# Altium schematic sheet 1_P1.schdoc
size 307 x 218 mm; Symbol: Sheet-Symbol_A4; Device: Sheet-Symbol_A4; @Project Name: Project Name; @Page Count: 3; @Update Date: 2021.11.05; @Create Date: 2024-11-23; @Schematic Name: Schematic Name; @Page No: 1; @Page Name: P1; Company: EasyEDA.com; Version: V1.0; Page Size: A4; @Create Time: 2:30:59 PM; @Update Time: 1:48:49 AM; Title Block Position: 3; Width: 1170; Height: 825; Region Start: 1; X Region Count: 6; Y Region Count: 4; Blade Width: 10; @Board Name: PENTASLAM
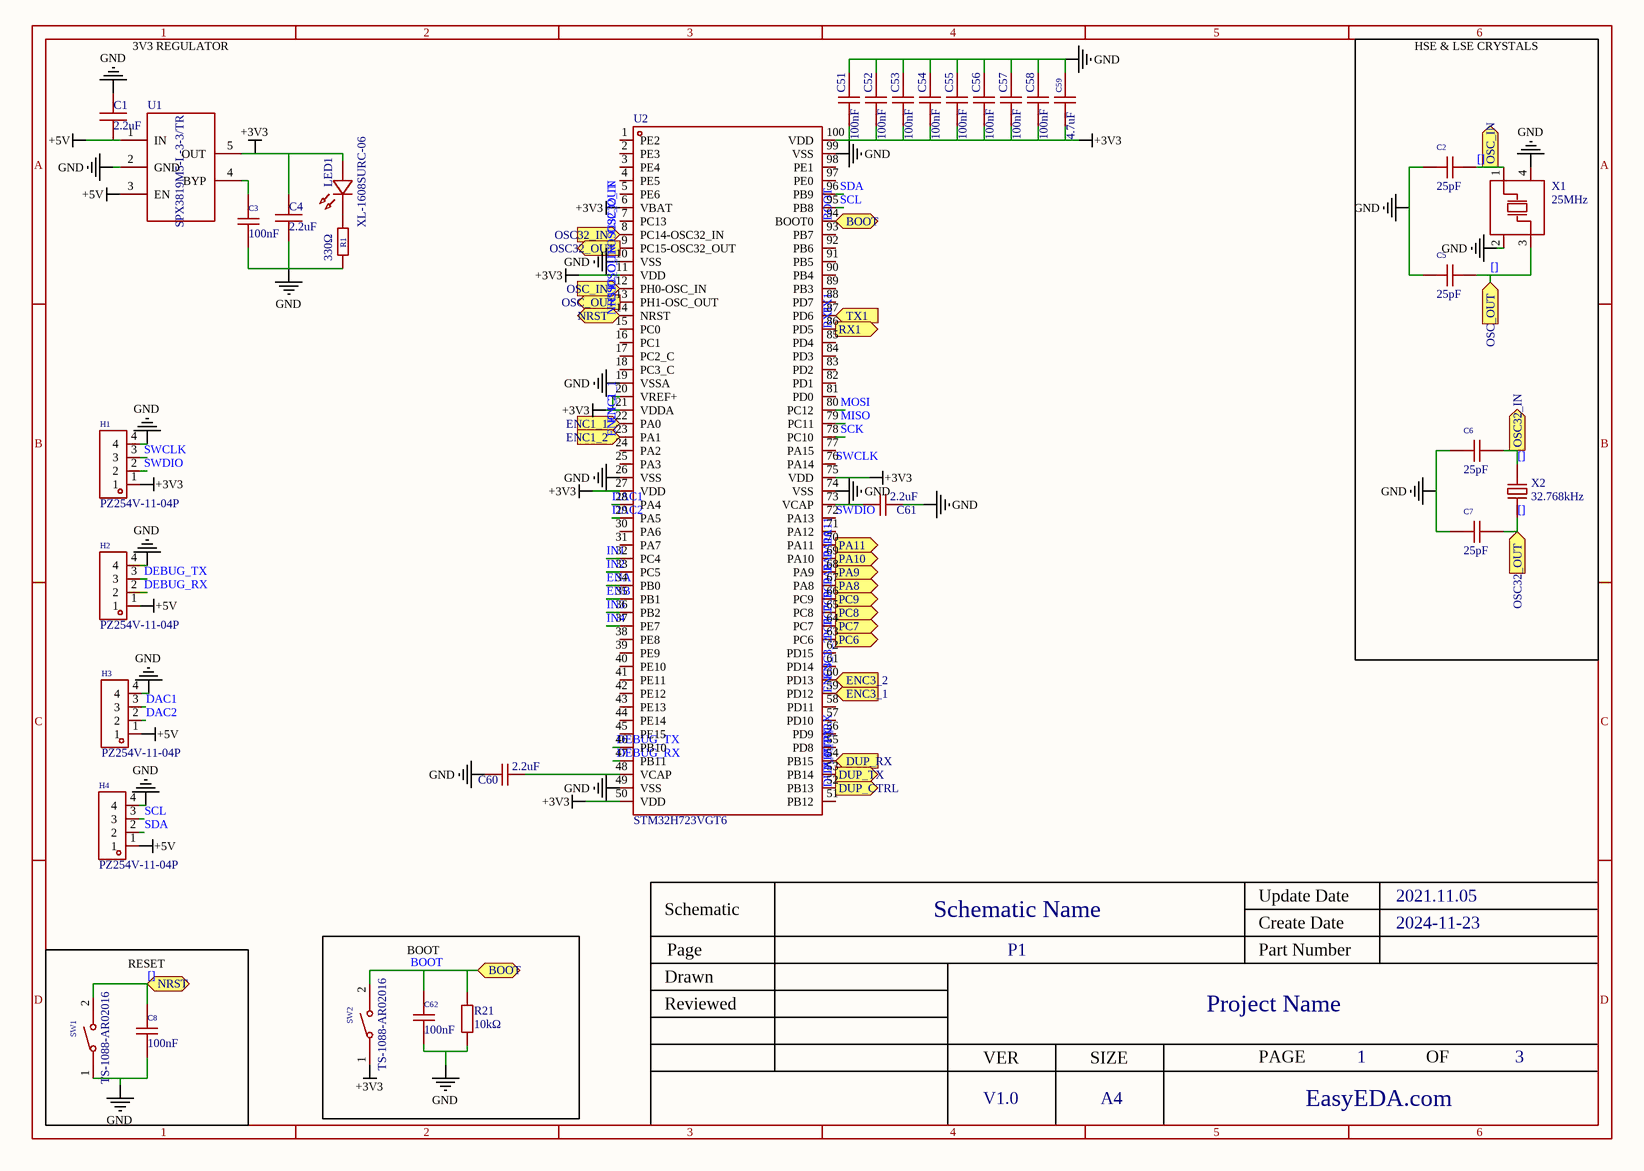
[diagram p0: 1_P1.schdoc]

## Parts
C1  2.2uF  [C0402]
C2  25pF  [C0402]
C3  100nF  [C0402]
C4  2.2uF  [C0402]
C5  25pF  [C0402]
C6  25pF  [C0402]
C7  25pF  [C0402]
C8  100nF  [C0402]
C51  100nF  [C0402]
C52  100nF  [C0402]
C53  100nF  [C0402]
C54  100nF  [C0402]
C55  100nF  [C0402]
C56  100nF  [C0402]
C57  100nF  [C0402]
C58  100nF  [C0402]
C59  4.7uF  [C0402]
C60  2.2uF  [C0402]
C61  2.2uF  [C0402]
C62  100nF  [C0402]
H1  PZ254V-11-04P  [HDR-TH_4P-P2.54-V-M]
H2  PZ254V-11-04P  [HDR-TH_4P-P2.54-V-M]
H3  PZ254V-11-04P  [HDR-TH_4P-P2.54-V-M]
H4  PZ254V-11-04P  [HDR-TH_4P-P2.54-V-M]
LED1  XL-1608SURC-06  [LED0603-RD_RED]
R1  330Ω  [R0402]
R21  10kΩ  [R0402]
SW1  TS-1088-AR02016  [SW-SMD_L3.9-W3.0-P4.45]
SW2  TS-1088-AR02016  [SW-SMD_L3.9-W3.0-P4.45]
U1  SPX3819M5-L-3-3/TR  [SOT-23-5_L3.0-W1.7-P0.95-LS2.8-BL]
U2  STM32H723VGT6  [LQFP-100_L14.0-W14.0-P0.50-LS16.0-BL]
X1  25MHz  [CRYSTAL-SMD_4P-L3.2-W2.5-BL]
X2  32.768kHz  [OSC-SMD_L3.2-W1.5]

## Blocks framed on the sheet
HSE & LSE CRYSTALS: C2 C5-C7 X1 X2
RESET: C8 SW1
BOOT: C62 R21 SW2

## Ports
BOOT (bidir), DUP_CTRL (out), DUP_RX (in), DUP_TX (out), ENC1_1 (in), ENC1_2 (in), ENC3_1 (in), ENC3_2 (in), NRST (bidir), OSC32_IN (in), OSC32_IN (out), OSC32_OUT (in), OSC32_OUT (out), OSC_IN (in), OSC_IN (out), OSC_OUT (in), OSC_OUT (out), PA8 (out), PA9 (out), PA10 (out), PA11 (out), PC6 (out), PC7 (out), PC8 (out), PC9 (out), RX1 (out), TX1 (in)

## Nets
+3V3: C4.2 C51.1 C52.1 C53.1 C54.1 C55.1 C56.1 C57.1 C58.1 C59.1 H1.1 LED1.2(A) SW2.1 U1.5(OUT) U2.6(VBAT) U2.11(VDD) U2.20(VREF+) U2.21(VDDA) U2.27(VDD) U2.50(VDD) U2.75(VDD) U2.100(VDD)
+5V: C1.1 H2.1 H3.1 H4.1 U1.1(IN) U1.3(EN)
GND: C1.2 C2.1 C3.1 C4.1 C5.1 C6.1 C7.1 C8.1 C51.2 C52.2 C53.2 C54.2 C55.2 C56.2 C57.2 C58.2 C59.2 C60.1 C61.2 C62.1 H1.4 H2.4 H3.4 H4.4 R1.1 R21.1 SW1.1 U1.2(GND) U2.10(VSS) U2.19(VSSA) U2.26(VSS) U2.49(VSS) U2.74(VSS) U2.99(VSS) X1.2(GND) X1.4(GND)
[]: C2.2 C5.2 C6.2 C7.2 C8.2 SW1.2 U2.8(PC14-OSC32_IN) U2.9(PC15-OSC32_OUT) U2.12(PH0-OSC_IN) U2.13(PH1-OSC_OUT) U2.14(NRST) X1.1(OSC1) X1.3(OSC2) X2.1 X2.2 ; port OSC_IN, port OSC_OUT, port OSC32_IN, port OSC32_OUT, port NRST  [also labelled NRST, OSC32_IN, OSC32_OUT, OSC_IN, OSC_OUT]
BOOT: C62.2 R21.2 SW2.2 U2.94(BOOT0) ; port BOOT
DAC1: H3.3 U2.28(PA4)
DAC2: H3.2 U2.29(PA5)
DEBUG_RX: H2.2 U2.47(PB11)
DEBUG_TX: H2.3 U2.46(PB10)
DUP_CTRL: U2.52(PB13) ; port DUP_CTRL
DUP_RX: U2.54(PB15) ; port DUP_RX
DUP_TX: U2.53(PB14) ; port DUP_TX
ENA: U2.34(PB0)
ENB: U2.35(PB1)
ENC1_1: U2.22(PA0) ; port ENC1_1
ENC1_2: U2.23(PA1) ; port ENC1_2
ENC3_1: U2.59(PD12) ; port ENC3_1
ENC3_2: U2.60(PD13) ; port ENC3_2
IN1: U2.32(PC4)
IN2: U2.33(PC5)
IN3: U2.36(PB2)
IN4: U2.37(PE7)
MISO: U2.79(PC11)
MOSI: U2.80(PC12)
PA8: U2.67(PA8) ; port PA8
PA9: U2.68(PA9) ; port PA9
PA10: U2.69(PA10) ; port PA10
PA11: U2.70(PA11) ; port PA11
PC6: U2.63(PC6) ; port PC6
PC7: U2.64(PC7) ; port PC7
PC8: U2.65(PC8) ; port PC8
PC9: U2.66(PC9) ; port PC9
RX1: U2.86(PD5) ; port RX1
SCK: U2.78(PC10)
SCL: H4.3 U2.95(PB8)
SDA: H4.2 U2.96(PB9)
SWCLK: H1.3 U2.76(PA14)
SWDIO: H1.2 U2.72(PA13)
TX1: U2.87(PD6) ; port TX1
NetC3_2: C3.2 U1.4(BYP)
NetC60_2: C60.2 U2.48(VCAP)
NetC61_1: C61.1 U2.73(VCAP)
NetLED1_1: LED1.1(K) R1.2

Not connected (* = marked no-connect by the designer): U2 1(PE2) 2(PE3) 3(PE4) 4(PE5) 5(PE6) 7(PC13) 15(PC0) 16(PC1) 17(PC2_C) 18(PC3_C) 24(PA2) 25(PA3) 30(PA6) 31(PA7) 38(PE8) 39(PE9) 40(PE10) 41(PE11) 42(PE12) 43(PE13) 44(PE14) 45(PE15) 51(PB12) 55(PD8) 56(PD9) 57(PD10) 58(PD11) 61(PD14) 62(PD15) 71(PA12) 77(PA15) 81(PD0) 82(PD1) 83(PD2) 84(PD3) 85(PD4) 88(PD7) 89(PB3) 90(PB4) 91(PB5) 92(PB6) 93(PB7) 97(PE0) 98(PE1)

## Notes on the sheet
- 3V3 REGULATOR

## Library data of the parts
C1 C4 = CL05A225MQ5NSNC: Manufacturer: SAMSUNG(三星); Add into BOM: yes; Tolerance: ±20%
C2 C5-C7 = TCC0402COG250K500AT: Manufacturer: CCTC(三环); Add into BOM: yes; Tolerance: ±10%
C3 = CC0402KRX7R7BB104: Manufacturer: YAGEO(国巨); Add into BOM: yes; Tolerance: ±10%
C8 C62 = CT41G-0402-2X1-16V-0.1μF-K(N): Manufacturer: TORCH(火炬); Add into BOM: yes; Tolerance: ±10%
C51-C58 = GRM155R71A104KA01D: Manufacturer: muRata(村田); Add into BOM: yes; Tolerance: ±10%
C59 = CL05A475KP5NRNC: Manufacturer: SAMSUNG(三星); Add into BOM: yes; Tolerance: ±10%
C60 C61 = GRM155R61A225KE95D: Manufacturer: muRata(村田); Add into BOM: yes; Tolerance: ±10%
H1-H4 = PZ254V-11-04P: Manufacturer: XFCN(兴飞); Symbol: PZ254V-11-04P_C2691448; Add into BOM: yes; Pin Structure: 1x4P; Pitch: 2.54mm; Circluar Pins/Square Pins: Square Pins; Current Rating (Max): 3A; Voltage Rating (Max): 250V
LED1 = XL-1608SURC-06: Manufacturer: XINGLIGHT(成兴光); Add into BOM: yes; Emitted Color: Red; Power Dissipation: 55mW; Forward Current: 25mA; Dominant Wavelength: 617nm~621nm; Peak Wavelength: 623nm; Lens Color: 无色透明透镜; Viewing Angle: 120°; Mounting Sytle: Positive post
R1 = 0402WGF3300TCE: Manufacturer: UNI-ROYAL(厚声); Add into BOM: yes; Tolerance: ±1%; Temperature Coefficient: ±100ppm/℃
R21 = RC0402FR-0710KL: Manufacturer: YAGEO(国巨); Add into BOM: yes; Tolerance: ±1%; Temperature Coefficient: ±100ppm/℃
SW1 SW2 = TS-1088-AR02016: Manufacturer: XUNPU(讯普); Add into BOM: yes; Circuit: SPST; Actuator Style: Round Button; Operating Force: 160gf; Switch Length: 4mm; Switch Width: 3mm; Switch Height: 2mm; Strike Gundam: 不带; Contact Current: 50mA; Voltage Rating (DC): 12V; Insulation Resistance: 100MΩ; Actuator/Cap Color: Black; Pin Style: SMDSplicing; Mechanical Life: 10万次
U1 = SPX3819M5-L-3-3/TR: Manufacturer: MaxLinear(迈凌); Add into BOM: yes; Output Type: Fixed; Maximum Input Voltage: 16V; Output Voltage: 3.3V; Output Current: 500mA; Power Supply Rejection Ratio (PSRR): 70dB; Dropout Voltage: 700mV@(500mA); standby current: 8uA; Output Polarity: Positive electrode; Number of Outputs: 1
U2 = STM32H723VGT6: Manufacturer: ST(意法半导体); Add into BOM: yes; Program Storage Size: 1MB; RAM Size: 564KB; GPIO Ports Number: 80; Operating Voltage Range: 1.71V~3.6V; CPU Maximum Speed: 550MHz; Program Memory Type: FLASH; ADC (Bit): 16bit; DAC (Bit): 12bit; Peripheral/Function: DMA；LCD/LED Driver
X1 = X322525MOB4SI: Manufacturer: YXC(扬兴晶振); Add into BOM: yes; Crystal Type: Surface Mount Crystal; Normal temperature Frequency Tolerance: ±10ppm; Frequency Stability(Full temperature range): ±20ppm
X2 = X321532768KGD2SI: Manufacturer: YXC(扬兴晶振); Add into BOM: yes; Crystal Type: Surface Mount Crystal; Normal temperature Frequency Tolerance: ±20ppm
